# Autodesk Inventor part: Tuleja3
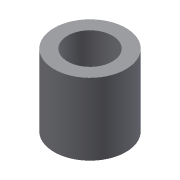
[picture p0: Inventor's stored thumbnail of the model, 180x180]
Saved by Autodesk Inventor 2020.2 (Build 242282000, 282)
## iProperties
Created: 2005-10
Part Number: Tuleja3
Document SubType Name: Modeling
Designer: F.Stasiak
Density: 1 g/cm^3
Material: Ogólny
Appearance: Domyślna
Manager: www.cadconsulting.pl
Company: Fabian Stasiak CAD Consulting
Author: F.Stasiak
Subject: Zbiór ćwiczeń. Autodesk Inventor 2020. Kurs podstawowy
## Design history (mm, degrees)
sketch "Szkic1"
  geometry: C1 r 40 at (0, 0); C2 r 25 at (0, 0); 1 further point
  constraints: 2 centre point, 2 coincident
  dimensions: "d0" = 80 diameter of C1; "d1" = 50 diameter of C2
extrude "Wyciągnięcie proste1" new body sketch "Szkic1" distance "d2" = 80; taper "d3" = 0 deg
node "Bryła1"
node "Korpusy bryłowe"
node "Korpusy powierzchniowe"
